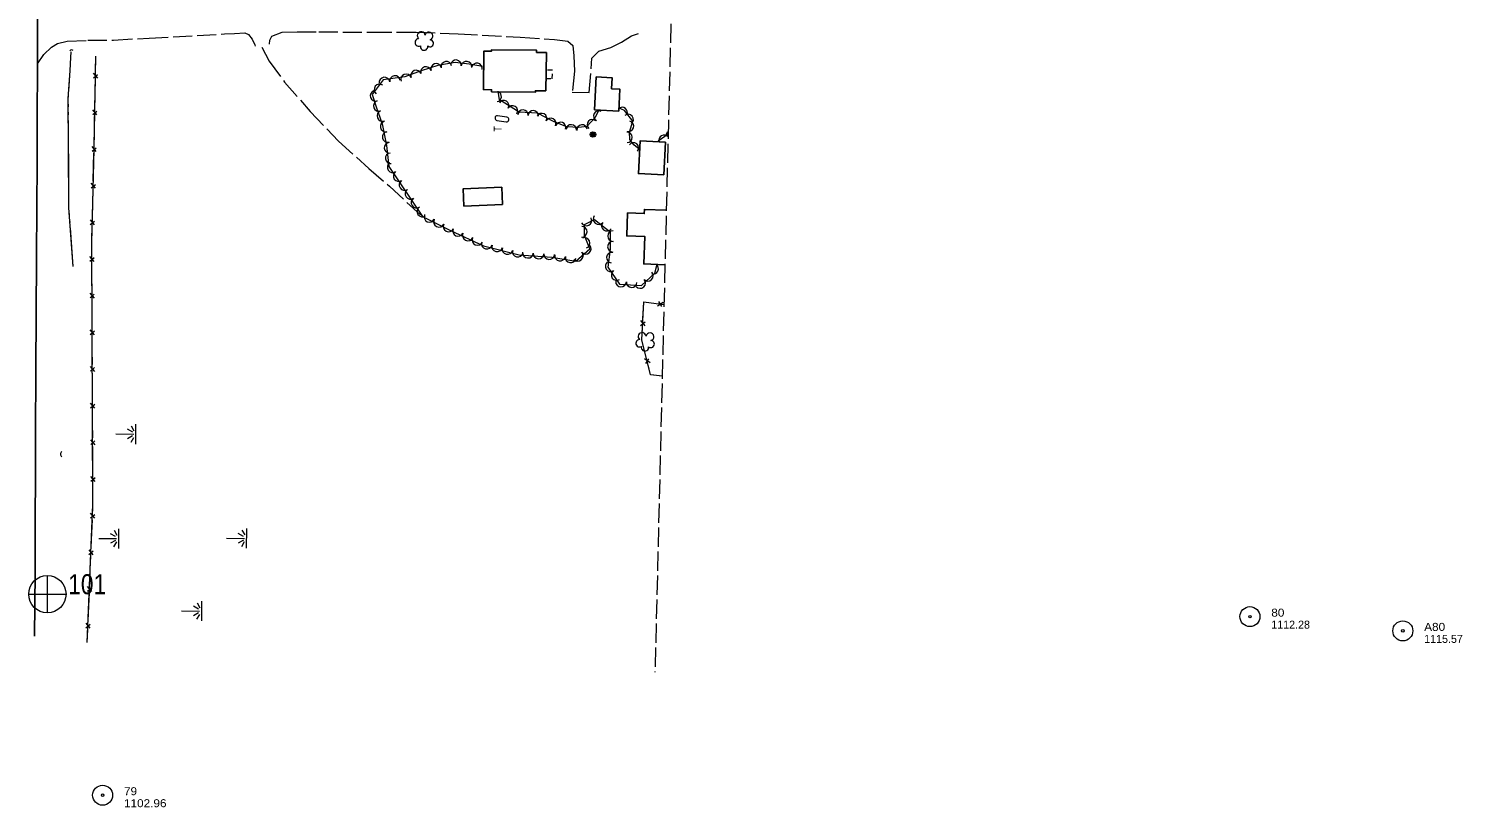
# Model space of a CAD drawing. Extents: x 296583 to 298831, y 44522 to 45957.
# Drawn here: x 297694 to 298769, y 44522 to 45106 of the extents above; entities that cross this region are included whole.
import ezdxf

# ---------------------------------------------------------------- set-up
doc = ezdxf.new("R2010")
doc.units = 0
doc.header["$LTSCALE"] = 2.4
doc.linetypes.add('LONG_DASHED', pattern=[7.5, 6, -1.5])
doc.linetypes.add('SHORT_DASHED', pattern=[2.7, 1.5, -1.2])
for name, color, linetype, lineweight in [('11', 7, 'Continuous', 25), ('12', 7, 'Continuous', 25), ('14', 7, 'Continuous', 13), ('15', 7, 'Continuous', 13), ('17', 7, 'LONG_DASHED', 13), ('18', 7, 'Continuous', 13), ('19', 7, 'Continuous', 13), ('4', 7, 'Continuous', 13), ('6', 7, 'Continuous', 13)]:
    doc.layers.add(name, color=color, linetype=linetype, lineweight=lineweight)

msp = doc.modelspace()

# ---------------------------------------------------------------- linework, layer by layer
at = {"layer": '11'}
msp.add_lwpolyline([(297698.38, 44650.533), (297698.706, 44698.102), (297698.849, 44741.788), (297698.978, 44766.95), (297699.154, 44802.183), (297699.396, 44849.707), (297699.6, 44892.48), (297699.874, 44933.693), (297700.193, 44973.23), (297700.282, 45004.18), (297700.352, 45038.221), (297700.604, 45078.854), (297700.618, 45127.759)], dxfattribs=at)
at = {"layer": '12', "lineweight": 13}
for p, q in [((298052.597, 45039.778), (298045.579, 45040.833)), ((298045.154, 45037.361), (298052.099, 45036.313))]:
    msp.add_line(p, q, dxfattribs=at)
at = {"layer": '12'}
for points in [[(298081.893, 45059.507), (298082.282, 45088.2), (298074.825, 45088.301), (298074.847, 45089.943), (298041.074, 45090.401), (298041.059, 45089.291), (298035.337, 45089.369), (298034.946, 45060.477), (298041.146, 45060.393), (298041.126, 45058.909), (298074.023, 45058.463), (298074.039, 45059.613)], [(298118.407, 45045.236), (298136.425, 45044.384), (298137.202, 45060.825), (298131.133, 45061.112), (298131.523, 45069.353), (298119.574, 45069.918)], [(298170.311, 44996.6), (298171.499, 45021.023), (298152.448, 45021.95), (298151.26, 44997.527)], [(298020.239, 44973.123), (298049.298, 44974.39), (298048.739, 44987.202), (298019.68, 44985.935)]]:
    msp.add_lwpolyline(points, close=True, dxfattribs=at)
msp.add_lwpolyline([(298172.125, 44969.957), (298155.675, 44970.594), (298155.556, 44967.521), (298143.096, 44968.004), (298142.429, 44950.786), (298156.071, 44950.258), (298155.274, 44929.688), (298171.125, 44929.074)], dxfattribs=at)
at = {"layer": '12', "lineweight": 13}
for centre, start, end in [((298045.426, 45039.09), 84.99867, 261.04599), ((298052.336, 45038.047), 262.18051, 81.4312)]:
    msp.add_arc(centre, 1.75, start, end, dxfattribs=at)
at = {"layer": '14'}
for centre, radius in [((298117.155, 45026.788), 2.018), ((298117.142, 45026.785), 1.518), ((298117.182, 45026.791), 1.008), ((298117.172, 45026.795), 0.502)]:
    msp.add_circle(centre, radius, dxfattribs=at)
at = {"layer": '15'}
for p, q in [((297744.097, 45074.32), (297744.312, 45085.491)), ((297742.518, 45069.166), (297745.7, 45071.865)), ((297745.71, 45068.937), (297742.585, 45072.666)), ((297743.784, 45058), (297743.972, 45067.825)), ((297743.569, 45046.829), (297743.784, 45058)), ((297741.989, 45041.675), (297745.171, 45044.373)), ((297745.182, 45041.445), (297742.056, 45045.175)), ((297743.255, 45030.508), (297743.444, 45040.334)), ((297743.04, 45019.337), (297743.255, 45030.508)), ((297741.455, 45014.19), (297744.649, 45016.875)), ((297744.654, 45013.954), (297741.528, 45017.683)), ((297742.671, 45003.018), (297742.904, 45012.843)), ((297742.407, 44991.848), (297742.671, 45003.018)), ((297740.804, 44986.701), (297743.998, 44989.386)), ((297743.996, 44986.458), (297740.887, 44990.201)), ((297742.021, 44975.53), (297742.253, 44985.354)), ((297741.757, 44964.36), (297742.021, 44975.53)), ((297740.154, 44959.213), (297743.348, 44961.897)), ((297743.346, 44958.969), (297740.237, 44962.712)), ((297741.371, 44948.041), (297741.603, 44957.865)), ((297743.1, 44931.525), (297739.887, 44935.179)), ((297739.902, 44931.679), (297743.02, 44934.452)), ((297741.432, 44920.546), (297741.389, 44930.373)), ((297741.482, 44909.372), (297741.432, 44920.546)), ((297743.221, 44904.029), (297740.009, 44907.683)), ((297740.024, 44904.183), (297743.141, 44906.956)), ((297741.554, 44893.05), (297741.51, 44902.876)), ((298154.664, 44888.853), (298155.235, 44900.473)), ((298165.583, 44898.193), (298169.787, 44901.022)), ((298166.17, 44901.475), (298168.617, 44897.884)), ((297741.603, 44881.876), (297741.554, 44893.05)), ((297743.343, 44876.533), (297740.13, 44880.187)), ((297740.146, 44876.686), (297743.263, 44879.46)), ((298152.86, 44883.538), (298156.255, 44886.248)), ((298156.176, 44883.2), (298153.039, 44887.179)), ((297741.675, 44865.553), (297741.632, 44875.38)), ((298156.874, 44860.611), (298154.067, 44871.901)), ((297741.725, 44854.38), (297741.675, 44865.553)), ((298159.953, 44855.635), (298155.801, 44858.538)), ((298156.681, 44855.001), (298159.15, 44858.576)), ((297743.465, 44849.037), (297740.252, 44852.691)), ((297740.267, 44849.19), (297743.385, 44851.964)), ((297741.797, 44838.057), (297741.753, 44847.884)), ((298169.083, 44845.657), (298162.905, 44846.328)), ((297741.846, 44826.884), (297741.797, 44838.057)), ((297743.586, 44821.541), (297740.373, 44825.195)), ((297740.389, 44821.694), (297743.506, 44824.468)), ((297741.919, 44810.561), (297741.875, 44820.388)), ((297741.968, 44799.388), (297741.919, 44810.561)), ((297743.708, 44794.045), (297740.495, 44797.699)), ((297740.511, 44794.198), (297743.628, 44796.972)), ((297742.04, 44783.065), (297741.997, 44792.892)), ((297742.09, 44771.892), (297742.04, 44783.065)), ((297743.83, 44766.548), (297740.617, 44770.203)), ((297740.632, 44766.702), (297743.749, 44769.475)), ((297742.162, 44755.569), (297742.118, 44765.396)), ((297740.299, 44739.282), (297743.54, 44741.91)), ((297743.486, 44738.983), (297740.444, 44742.78)), ((297741.319, 44728.091), (297741.724, 44737.909)), ((297740.858, 44716.927), (297741.319, 44728.091)), ((297739.165, 44711.809), (297742.406, 44714.437)), ((297742.352, 44711.51), (297739.309, 44715.307)), ((297740.185, 44700.618), (297740.59, 44710.437)), ((297739.724, 44689.454), (297740.185, 44700.618)), ((297738.031, 44684.336), (297741.271, 44686.964)), ((297741.218, 44684.037), (297738.175, 44687.834)), ((297738.589, 44661.981), (297739.05, 44673.145)), ((297739.05, 44673.145), (297739.456, 44682.964)), ((297736.896, 44656.863), (297740.137, 44659.491)), ((297740.083, 44656.564), (297737.041, 44660.361)), ((297737.916, 44645.672), (297738.321, 44655.491))]:
    msp.add_line(p, q, dxfattribs=at)
for points in [[(297737.916, 44645.672), (297742.19, 44749.19), (297741.32, 44945.898), (297742.968, 45015.569), (297744.312, 45085.491)], [(297741.36, 44936.869), (297741.32, 44945.898), (297741.371, 44948.041)], [(298169.083, 44845.657), (298160.357, 44846.604), (298153.87, 44872.694), (298155.275, 44901.284), (298170.398, 44899.392)], [(298155.235, 44900.473), (298155.275, 44901.284), (298164.622, 44900.115)], [(298154.067, 44871.901), (298153.87, 44872.694), (298154.332, 44882.097)], [(298162.905, 44846.328), (298160.357, 44846.604), (298158.506, 44854.047)], [(297741.992, 44744.4), (297742.19, 44749.19), (297742.162, 44755.569)]]:
    msp.add_lwpolyline(points, dxfattribs=at)
for centre, radius, start, end in [((297726.161, 45088.684), 1.565, 39.12248, 145.36204), ((297720.173, 44787.077), 2.406, 127.99573, 234.23529)]:
    msp.add_arc(centre, radius, start, end, dxfattribs=at)
at = {"layer": '17'}
for points in [[(297700.604, 45079.89), (297705.264, 45086.844), (297711.05, 45092.24), (297715.658, 45094.959), (297722.703, 45096.845), (297738.217, 45097.409), (297757.479, 45097.603), (297784.284, 45099.126), (297840.903, 45102.18), (297848.25, 45102.513), (297856.048, 45103.082), (297858.817, 45101.875), (297861.461, 45098.183), (297863.447, 45094.131), (297863.931, 45093.041)], [(297874.588, 45094.629), (297874.738, 45097.585), (297876.395, 45100.601), (297884.042, 45103.458), (297895.218, 45103.684), (297911.536, 45103.786), (297951.851, 45103.429), (297984.499, 45103.648), (298016.072, 45102.166), (298062.649, 45099.749), (298088.228, 45098.072), (298098.373, 45096.819), (298101.964, 45093.588), (298102.921, 45085.76), (298103.236, 45074.162), (298101.601, 45058.422), (298114.394, 45058.17), (298116.335, 45084.051), (298121.495, 45089.235), (298130.534, 45092.027), (298138.448, 45095.921), (298145.954, 45100.795), (298151.259, 45102.476)], [(297868.824, 45092.25), (297874.244, 45081.85), (297885.913, 45066.152), (297905.134, 45044.089), (297926.366, 45021.763), (297949.157, 45001.312), (297964.466, 44988.087), (297987.698, 44966.547)]]:
    msp.add_lwpolyline(points, dxfattribs=at)
at = {"layer": '17', "linetype": 'SHORT_DASHED'}
msp.add_lwpolyline([(298082.02, 45068.856), (298086.619, 45068.642), (298086.767, 45074.933), (298082.105, 45075.173)], dxfattribs=at)
at = {"layer": '18'}
msp.add_line((298173.523, 45027.06), (298166.138, 45021.746), dxfattribs=at)
for points in [[(298034.417, 45077.675), (298024.286, 45079.49), (298013.764, 45080.888), (298000.699, 45078.46), (297988.268, 45074.656), (297975.947, 45069.918), (297959.929, 45067.709), (297951.613, 45056.757), (297954.592, 45047.583), (297959.151, 45034.886), (297962.36, 45018.532), (297964.014, 45002.829), (297989.325, 44965.183), (298010.384, 44954.763), (298035.015, 44943.402), (298061.741, 44936.515), (298086.356, 44934.833), (298104.369, 44931.823), (298114.915, 44941.103), (298110.779, 44950.945), (298110.883, 44959.26), (298118.244, 44963.128), (298130.089, 44953.777), (298130.074, 44940.845), (298128.342, 44927.224), (298137.027, 44914.441), (298153.664, 44913.616), (298163.549, 44922.801), (298165.204, 44929.5)], [(298121.495, 45045.056), (298118.422, 45039.222), (298112.549, 45032.685), (298106.628, 45032.008), (298097.541, 45032.513), (298087.947, 45036.183), (298075.656, 45042.672), (298061.918, 45043.603), (298047.085, 45052.902), (298046.009, 45059.376)], [(298152.142, 45016.401), (298150.629, 45016.845), (298147.857, 45019.018), (298144.736, 45023.119), (298144.668, 45028.642), (298147.096, 45036.898), (298140.763, 45044.737), (298136.405, 45046.773)]]:
    msp.add_lwpolyline(points, dxfattribs=at)
for centre, radius, start, end in [((297988.354, 45100.815), 2.974, 7.98733, 229.22121), ((297994.206, 45100.659), 2.975, 285.63814, 168.61141), ((297986.458, 45095.787), 2.777, 90.95822, 298.73121), ((297990.511, 45092.756), 2.783, 167.63523, 8.64628), ((297994.929, 45095.185), 2.611, 230.34337, 88.27598), ((298007.17, 45077.533), 4.001, 10.53541, 190.52009), ((298014.385, 45078.693), 4.001, 352.43941, 172.42409), ((298022.316, 45077.639), 4.001, 352.43941, 172.42409), ((297968.694, 45066.804), 4.001, 7.85964, 187.84432), ((297977.063, 45068.103), 4.001, 21.04174, 201.02642), ((297984.53, 45070.975), 4.001, 21.04174, 201.02642), ((297991.932, 45073.587), 4.001, 17.02225, 197.00693), ((297999.582, 45075.928), 4.001, 17.02225, 197.00693), ((298030.11, 45076.319), 4.001, 349.8507, 169.83537), ((297957.096, 45060.515), 4.001, 52.79777, 232.78245), ((297960.768, 45065.711), 4.001, 7.85964, 187.84432), ((297954.127, 45055.794), 4.001, 107.99742, 287.98209), ((297956.579, 45048.246), 4.001, 109.75891, 289.74358), ((298044.651, 45055.246), 3.853, 279.44415, 68.99546), ((298050.245, 45048.541), 3.853, 327.92353, 147.90821), ((297959.282, 45040.716), 4.001, 109.75891, 289.74358), ((298056.772, 45044.449), 3.853, 327.92353, 147.90821), ((298064.67, 45041.395), 3.853, 356.13076, 176.11543), ((298072.357, 45040.875), 3.853, 356.13076, 176.11543), ((298078.724, 45038.772), 3.853, 332.17597, 152.16065), ((298085.537, 45035.175), 3.853, 332.17597, 152.16065), ((298121.484, 45040.708), 3.853, 62.2301, 242.21478), ((298139.092, 45043.249), 3.927, 334.9663, 131.08589), ((298143.544, 45038.023), 3.927, 308.94184, 128.92652), ((297961.698, 45032.779), 4.001, 101.10926, 281.09393), ((297963.239, 45024.928), 4.001, 101.10926, 281.09393), ((298092.872, 45032.14), 3.853, 339.07427, 159.05895), ((298100.9, 45030.307), 3.853, 356.82678, 176.81146), ((298108.923, 45030.241), 3.853, 6.53047, 186.51514), ((298116.605, 45034.182), 3.853, 48.07037, 228.05504), ((298142.662, 45024.622), 3.927, 270.71306, 90.69774), ((298143.785, 45032.924), 3.927, 253.61963, 73.6043), ((298175.635, 45025.438), 3.918, 121.89881, 171.14153), ((297964.641, 45016.868), 4.001, 96.02047, 276.00514), ((298147.511, 45016.677), 3.927, 321.91439, 141.89907), ((298170.515, 45022.369), 3.918, 41.01582, 196.54762), ((297965.479, 45008.911), 4.001, 96.02047, 276.00514), ((297966.926, 45002.25), 4.001, 123.92227, 303.90695), ((297971.39, 44995.611), 4.001, 123.92227, 303.90695), ((297975.855, 44988.971), 4.001, 123.92227, 303.90695), ((297980.319, 44982.332), 4.001, 123.92227, 303.90695), ((297984.783, 44975.692), 4.001, 123.92227, 303.90695), ((297989.247, 44969.052), 4.001, 123.92227, 303.90695), ((297994.507, 44964.955), 4.001, 153.68144, 333.66612), ((298001.678, 44961.407), 4.001, 153.68144, 333.66612), ((298112.181, 44962.307), 4.001, 207.72833, 27.71301), ((298121.309, 44963.376), 4.001, 141.71844, 321.70312), ((298008.849, 44957.859), 4.001, 153.68144, 333.66612), ((298016.031, 44954.465), 4.001, 155.24624, 335.23092), ((298023.296, 44951.114), 4.001, 155.24624, 335.23092), ((298108.721, 44953.852), 4.001, 269.29107, 89.27575), ((298127.588, 44958.419), 4.001, 141.71844, 321.70312), ((298132.179, 44950.613), 4.001, 89.9412, 269.92588), ((298030.561, 44947.762), 4.001, 155.24624, 335.23092), ((298037.6, 44944.898), 4.001, 165.55753, 345.54221), ((298045.348, 44942.902), 4.001, 165.55753, 345.54221), ((298053.095, 44940.905), 4.001, 165.55753, 345.54221), ((298111.696, 44941.06), 4.001, 221.35397, 41.33865), ((298110.832, 44945.414), 4.001, 292.80174, 112.78642), ((298132.17, 44942.612), 4.001, 89.9412, 269.92588), ((298060.843, 44938.909), 4.001, 165.55753, 345.54221), ((298068.402, 44938.159), 4.001, 176.09859, 356.08326), ((298076.384, 44937.613), 4.001, 176.09859, 356.08326), ((298084.366, 44937.068), 4.001, 176.09859, 356.08326), ((298092.484, 44935.932), 4.001, 170.5211, 350.50577), ((298100.376, 44934.613), 4.001, 170.5211, 350.50577), ((298105.69, 44935.775), 4.001, 221.35397, 41.33865), ((298130.356, 44927.986), 4.001, 124.20056, 304.18523), ((298131.365, 44934.399), 4.001, 82.76101, 262.74569), ((298134.852, 44921.368), 4.001, 124.20056, 304.18523), ((298158.387, 44920.863), 4.001, 222.90546, 42.89013), ((298162.212, 44926.119), 4.001, 256.13051, 53.29324), ((298138.178, 44916.48), 4.001, 177.16879, 357.15347), ((298146.169, 44916.084), 4.001, 177.16879, 357.15347), ((298152.526, 44915.417), 4.001, 222.90546, 42.89013), ((298153.991, 44875.224), 2.974, 7.98733, 229.22121), ((298159.843, 44875.068), 2.975, 285.63814, 168.61141), ((298152.095, 44870.196), 2.777, 90.95822, 298.73121), ((298156.148, 44867.165), 2.783, 167.63523, 8.64628), ((298160.566, 44869.594), 2.611, 230.34337, 88.27598)]:
    msp.add_arc(centre, radius, start, end, dxfattribs=at)
at = {"layer": '19'}
for p, q in [((297723.729, 45047.474), (297723.718, 45049.49)), ((297723.765, 45041.428), (297723.753, 45043.444)), ((297724.136, 44978.948), (297723.962, 45008.174)), ((297724.172, 44972.901), (297724.16, 44974.916)), ((297724.536, 44966.868), (297724.388, 44968.878)), ((297724.982, 44960.839), (297724.834, 44962.848)), ((297727.436, 44927.677), (297725.28, 44956.819)), ((297759.3, 44802.191), (297772.719, 44802.089)), ((297771.96, 44803.525), (297768.127, 44805.754)), ((297770.842, 44808.319), (297772.904, 44804.618)), ((297774.313, 44794.652), (297774.425, 44809.446)), ((297771.939, 44800.72), (297768.072, 44798.549)), ((297770.747, 44795.944), (297772.865, 44799.613)), ((297759.116, 44725.176), (297755.283, 44727.405)), ((297757.998, 44729.97), (297760.06, 44726.269)), ((297761.469, 44716.303), (297761.581, 44731.097)), ((297855.018, 44725.354), (297851.185, 44727.583)), ((297853.9, 44730.148), (297855.962, 44726.447)), ((297857.371, 44716.481), (297857.483, 44731.275)), ((297746.456, 44723.842), (297759.875, 44723.74)), ((297759.095, 44722.371), (297755.228, 44720.2)), ((297757.903, 44717.595), (297760.021, 44721.264)), ((297842.358, 44724.02), (297855.777, 44723.918)), ((297854.997, 44722.549), (297851.13, 44720.378)), ((297853.805, 44717.773), (297855.923, 44721.442)), ((297821.343, 44670.806), (297817.51, 44673.035)), ((297820.225, 44675.6), (297822.287, 44671.899)), ((297823.696, 44661.933), (297823.808, 44676.727)), ((297808.683, 44669.472), (297822.102, 44669.37)), ((297821.322, 44668.001), (297817.455, 44665.83)), ((297820.13, 44663.225), (297822.248, 44666.894))]:
    msp.add_line(p, q, dxfattribs=at)
for points in [[(297727.436, 44927.677), (297724.179, 44971.698), (297723.911, 45016.747), (297723.693, 45053.636), (297725.143, 45074.88), (297725.568, 45084.47), (297725.743, 45088.727)], [(297724.097, 45059.553), (297725.143, 45074.88), (297725.568, 45084.47), (297725.743, 45088.727)], [(297723.694, 45053.52), (297723.693, 45053.636), (297723.822, 45055.531)], [(297723.962, 45008.174), (297723.911, 45016.747), (297723.789, 45037.398)]]:
    msp.add_lwpolyline(points, dxfattribs=at)
at = {"layer": '4', "linetype": 'LONG_DASHED'}
msp.add_line((298192.285, 45793.642), (298163.649, 44623.641), dxfattribs=at)
at = {"layer": '4'}
for p, q in [((297707.908, 44696.082), (297707.843, 44668.228)), ((297693.999, 44682.052), (297721.904, 44682.039))]:
    msp.add_line(p, q, dxfattribs=at)
msp.add_circle((297707.96, 44682.06), 14, dxfattribs=at)
at = {"layer": '6'}
for centre, radius in [((298609.851, 44665.183), 7.5), ((298609.851, 44665.183), 0.96), ((298724.516, 44654.507), 7.5), ((298724.516, 44654.507), 0.96), ((297749.428, 44531.264), 7.5), ((297749.428, 44531.264), 0.96)]:
    msp.add_circle(centre, radius, dxfattribs=at)

# ---------------------------------------------------------------- texts
at = {"layer": '12', "width": 0.85}
msp.add_text('T', height=6, rotation=89.564, dxfattribs=at).set_placement((298048.687, 45028.852))
at = {"layer": '4', "width": 0.85}
msp.add_text('101', height=15, dxfattribs=at).set_placement((297723.612, 44681.99))
at = {"layer": '6', "width": 1.1}
for s, p in [('80', (298625.851, 44665.183)), ('A80', (298740.516, 44654.507)), ('79', (297765.428, 44531.264)), ('1102.96', (297765.428, 44522.264))]:
    msp.add_text(s, height=6, dxfattribs=at).set_placement(p)
at = {"layer": '6'}
for s, p in [('1112.28', (298625.851, 44656.183)), ('1115.57', (298740.516, 44645.507))]:
    msp.add_text(s, height=6, dxfattribs=at).set_placement(p)

doc.saveas('drawing.dxf')
